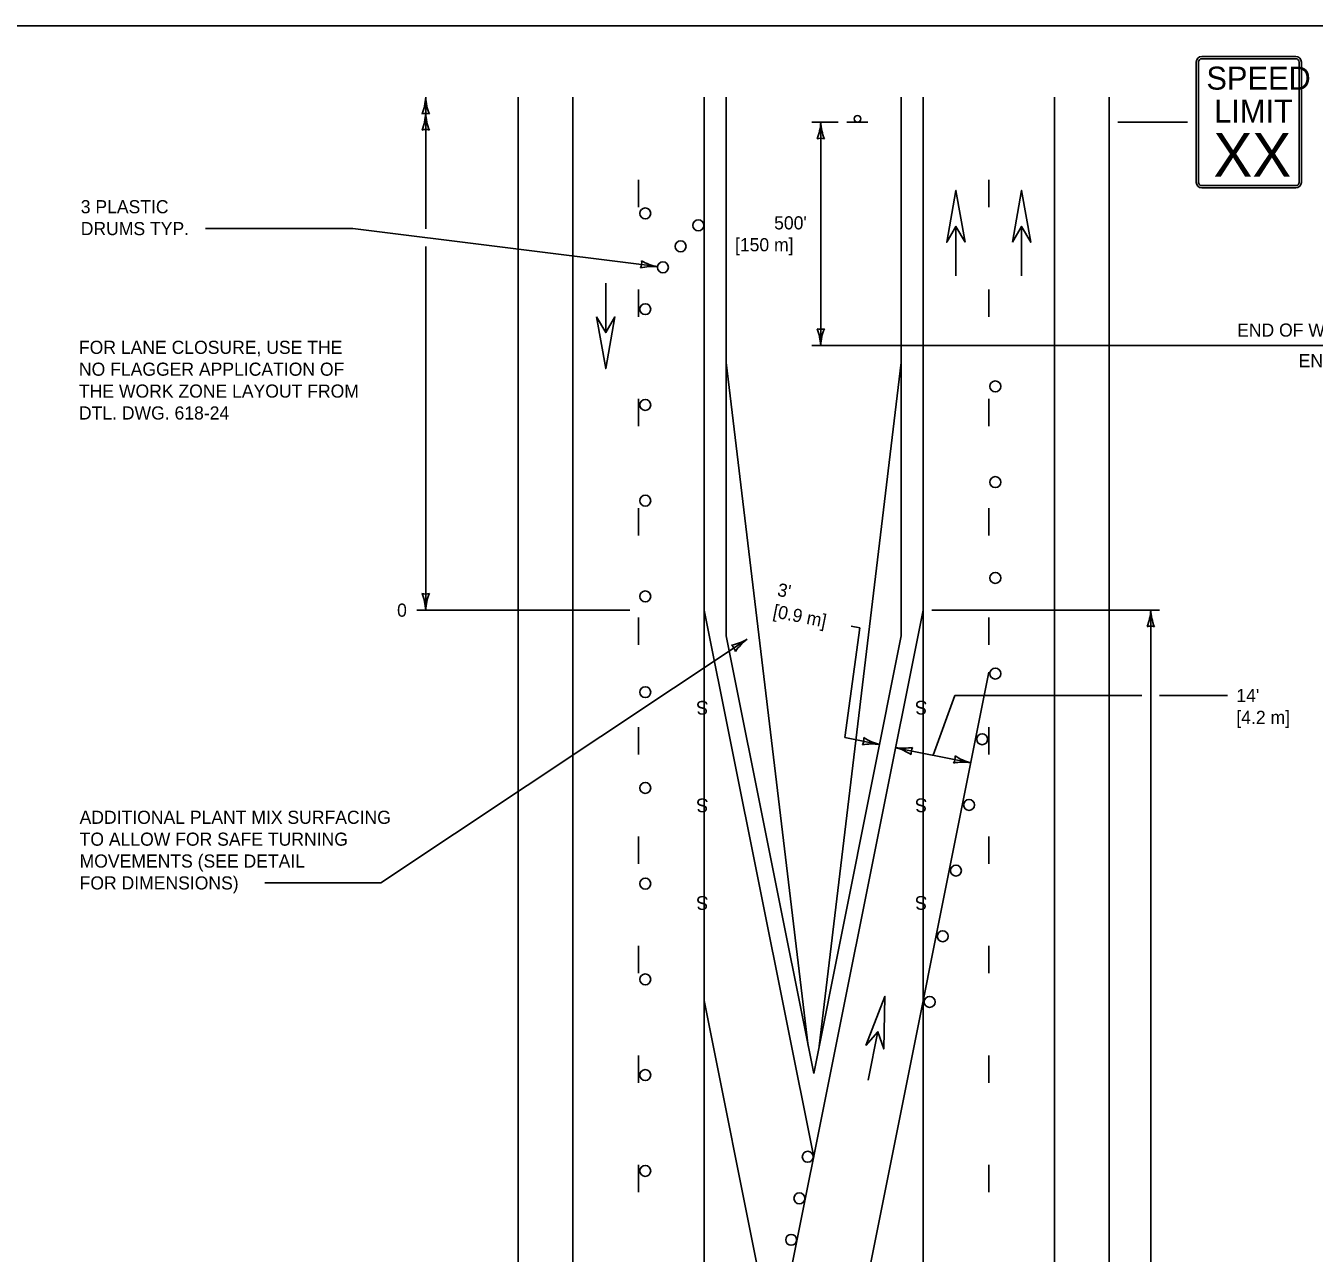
# Model space of a CAD drawing. Extents: x 49991.4 to 50021, y 49987.6 to 50011.4.
# Drawn here: x 50005.06 to 50010.95, y 49993.39 to 49999 of the extents above; entities that cross this region are included whole.
import ezdxf

# ---------------------------------------------------------------- set-up
doc = ezdxf.new("R2010")
doc.units = 0
for name, color, linetype in [('Level 1', 7, 'Continuous'), ('Level 2', 7, 'Continuous'), ('Level 3', 7, 'Continuous')]:
    doc.layers.add(name, color=color, linetype=linetype)

msp = doc.modelspace()

# ---------------------------------------------------------------- linework, layer by layer
at = {"layer": 'Level 1'}
for p, q in [((50010.4382, 49998.8586), (50010.8682, 49998.8586)), ((50010.4382, 49998.8486), (50010.8682, 49998.8486)), ((50010.4132, 49998.2836), (50010.4132, 49998.8336)), ((50010.4232, 49998.2836), (50010.4232, 49998.8336)), ((50010.8832, 49998.8336), (50010.8832, 49998.2836)), ((50010.8932, 49998.8336), (50010.8932, 49998.2836)), ((50007.315, 49988.2392), (50007.315, 49998.6725)), ((50007.565, 49988.2392), (50007.565, 49998.6725)), ((50008.165, 49996.3289), (50008.165, 49998.6725)), ((50008.265, 49996.2111), (50008.265, 49998.6725)), ((50009.065, 49996.2117), (50009.065, 49998.6725)), ((50009.165, 49996.3295), (50009.165, 49998.6725)), ((50009.765, 49988.1793), (50009.765, 49998.6725)), ((50010.015, 49988.1793), (50010.015, 49998.6725)), ((50008.913, 49998.5587), (50008.817, 49998.5587)), ((50007.865, 49998.1697), (50007.865, 49998.2947)), ((50009.465, 49998.1697), (50009.465, 49998.2947)), ((50010.8682, 49998.2686), (50010.4382, 49998.2686)), ((50010.8682, 49998.2586), (50010.4382, 49998.2586)), ((50009.3148, 49997.8565), (50009.3148, 49998.0823)), ((50009.315, 49997.8565), (50009.315, 49998.0823)), ((50009.6149, 49997.8565), (50009.6149, 49998.0823)), ((50009.6151, 49997.8565), (50009.6151, 49998.0823)), ((50007.7149, 49997.8226), (50007.7149, 49997.5968)), ((50007.7151, 49997.8226), (50007.7151, 49997.5968)), ((50007.865, 49997.6697), (50007.865, 49997.7947)), ((50009.465, 49997.6697), (50009.465, 49997.7947)), ((50008.265, 49997.4611), (50008.6399, 49994.3368)), ((50009.065, 49997.4611), (50008.6901, 49994.3368)), ((50007.865, 49997.1697), (50007.865, 49997.2947)), ((50009.465, 49997.1697), (50009.465, 49997.2947)), ((50007.865, 49996.6697), (50007.865, 49996.7947)), ((50009.465, 49996.6697), (50009.465, 49996.7947)), ((50007.865, 49989.8293), (50009.165, 49996.3295)), ((50008.165, 49994.5446), (50008.165, 49996.3289)), ((50008.665, 49993.8292), (50008.165, 49996.3289)), ((50009.165, 49994.5449), (50009.165, 49996.3295)), ((50007.865, 49996.1697), (50007.865, 49996.2947)), ((50009.465, 49996.1697), (50009.465, 49996.2947)), ((50008.665, 49994.2114), (50008.265, 49996.2111)), ((50008.665, 49994.2114), (50009.065, 49996.2117)), ((50008.165, 49989.5449), (50009.465, 49996.0449)), ((50007.865, 49995.6697), (50007.865, 49995.7947)), ((50009.465, 49995.6697), (50009.465, 49995.7947)), ((50007.865, 49995.1697), (50007.865, 49995.2947)), ((50009.465, 49995.1697), (50009.465, 49995.2947)), ((50007.865, 49994.6697), (50007.865, 49994.7947)), ((50009.465, 49994.6697), (50009.465, 49994.7947)), ((50008.165, 49991.3293), (50008.165, 49994.5446)), ((50008.4865, 49992.937), (50008.165, 49994.5446)), ((50009.165, 49991.3292), (50009.165, 49994.5449)), ((50008.9138, 49994.1814), (50008.9585, 49994.4029)), ((50008.914, 49994.1814), (50008.9587, 49994.4029)), ((50007.865, 49994.1697), (50007.865, 49994.2947)), ((50009.465, 49994.1697), (50009.465, 49994.2947)), ((50007.865, 49993.6697), (50007.865, 49993.7947)), ((50009.465, 49993.6697), (50009.465, 49993.7947))]:
    msp.add_line(p, q, dxfattribs=at)
for points in [[(49999.3835, 49998.9992), (50016.7501, 49998.9992), (50016.7501, 49987.7988), (49999.3835, 49987.7988)], [(50009.3568, 49998.0101), (50009.315, 49998.2465), (50009.2732, 49998.0101), (50009.315, 49998.0821)], [(50009.5731, 49998.0101), (50009.6149, 49998.2465), (50009.6567, 49998.0101), (50009.6149, 49998.0821)], [(50007.6731, 49997.669), (50007.7149, 49997.4326), (50007.7567, 49997.669), (50007.7149, 49997.597)], [(50008.903, 49994.3404), (50008.9908, 49994.5639), (50008.985, 49994.3238), (50008.9584, 49994.4028)]]:
    msp.add_lwpolyline(points, close=True, dxfattribs=at)
for centre, radius in [((50008.8651, 49998.5739), 0.0152), ((50007.8952, 49998.1417), 0.025), ((50008.1378, 49998.0873), 0.025), ((50008.0569, 49997.9913), 0.025), ((50007.9761, 49997.8954), 0.025), ((50007.8952, 49997.7042), 0.025), ((50009.4949, 49997.3514), 0.025), ((50007.8952, 49997.2667), 0.025), ((50009.4949, 49996.9139), 0.025), ((50007.8952, 49996.8292), 0.025), ((50009.4949, 49996.4764), 0.025), ((50007.8952, 49996.3917), 0.025), ((50009.4949, 49996.0389), 0.025), ((50007.8952, 49995.9542), 0.025), ((50009.4349, 49995.7389), 0.025), ((50007.8952, 49995.5167), 0.025), ((50009.3749, 49995.4389), 0.025), ((50009.3149, 49995.1389), 0.025), ((50007.8953, 49995.0793), 0.025), ((50009.2549, 49994.8389), 0.025), ((50007.8953, 49994.6418), 0.025), ((50009.1949, 49994.5389), 0.025), ((50007.8953, 49994.2043), 0.025), ((50008.6377, 49993.8311), 0.025), ((50007.8953, 49993.7668), 0.025), ((50008.5998, 49993.6413), 0.025), ((50008.562, 49993.4517), 0.025)]:
    msp.add_circle(centre, radius, dxfattribs=at)
for centre, radius, start, end in [((50010.4382, 49998.8336), 0.025, 90, 180), ((50010.4382, 49998.8336), 0.015, 90, 180), ((50010.8682, 49998.8336), 0.025, 0, 90), ((50010.8682, 49998.8336), 0.015, 0, 90), ((50010.4382, 49998.2836), 0.025, 180, 270), ((50010.4382, 49998.2836), 0.015, 180, 270), ((50010.8682, 49998.2836), 0.025, 270, 0), ((50010.8682, 49998.2836), 0.015, 270, 0)]:
    msp.add_arc(centre, radius, start, end, dxfattribs=at)
at = {"layer": 'Level 3'}
for p, q in [((50006.892, 49998.6723), (50006.892, 49998.0708)), ((50008.697, 49998.5586), (50008.657, 49998.5586)), ((50008.697, 49998.5586), (50008.697, 49997.5387)), ((50008.777, 49998.5586), (50008.697, 49998.5586)), ((50010.055, 49998.5586), (50010.3732, 49998.5586)), ((50005.8866, 49998.0724), (50006.5588, 49998.0724)), ((50006.5588, 49998.0724), (50007.9513, 49997.8985)), ((50006.892, 49997.9908), (50006.892, 49996.3289)), ((50008.697, 49997.5387), (50008.657, 49997.5387)), ((50011.6515, 49997.5387), (50008.697, 49997.5387)), ((50006.852, 49996.3289), (50007.825, 49996.3289)), ((50010.245, 49996.3295), (50009.205, 49996.3295)), ((50010.205, 49996.3295), (50010.205, 49989.5447)), ((50006.6874, 49995.0825), (50008.3613, 49996.1965)), ((50009.2108, 49995.6662), (50009.31, 49995.939)), ((50010.165, 49995.939), (50009.31, 49995.939)), ((50010.5563, 49995.939), (50010.245, 49995.939)), ((50008.9657, 49995.715), (50008.8079, 49995.7464)), ((50009.0392, 49995.7003), (50009.3824, 49995.632)), ((50006.6874, 49995.0825), (50006.1566, 49995.0825))]:
    msp.add_line(p, q, dxfattribs=at)
msp.add_lwpolyline([(50008.8361, 49996.2558), (50008.8753, 49996.248), (50008.8079, 49995.7464)], dxfattribs=at)
for centre, radius, start, end in [((50006.6699, 49998.6815), 0.2223, 337.45601, 357.63952), ((50007.1247, 49998.6838), 0.233, 182.82731, 202.07716), ((50006.892, 49998.5441), 0.0548, 72.13882, 107.86118), ((50006.6699, 49998.6081), 0.2223, 337.45601, 357.63952), ((50007.1247, 49998.6104), 0.233, 182.82731, 202.07716), ((50008.4749, 49998.5678), 0.2223, 337.45601, 357.63952), ((50008.9297, 49998.5701), 0.233, 182.82731, 202.07716), ((50006.892, 49998.4707), 0.0548, 72.13882, 107.86118), ((50008.697, 49998.4304), 0.0548, 72.13882, 107.86118), ((50007.8243, 49997.9163), 0.0548, 334.13882, 9.86118), ((50007.9302, 49997.6664), 0.233, 84.82731, 104.07716), ((50007.9912, 49998.1172), 0.2223, 239.45601, 259.63952), ((50008.697, 49997.667), 0.0548, 252.13882, 287.86118), ((50008.4643, 49997.5272), 0.233, 2.82731, 22.07716), ((50008.9191, 49997.5296), 0.2223, 157.45601, 177.63952), ((50006.892, 49996.4571), 0.0548, 252.13882, 287.86118), ((50006.6593, 49996.3174), 0.233, 2.82731, 22.07716), ((50007.1141, 49996.3197), 0.2223, 157.45601, 177.63952), ((50009.9829, 49996.3387), 0.2223, 337.45601, 357.63952), ((50010.4377, 49996.341), 0.233, 182.82731, 202.07716), ((50010.205, 49996.2013), 0.0548, 72.13882, 107.86118), ((50008.2459, 49996.3865), 0.2223, 281.10024, 301.28375), ((50008.4998, 49996.0091), 0.233, 126.47154, 145.72139), ((50008.2546, 49996.1255), 0.0548, 15.78305, 51.50541), ((50008.8401, 49995.7408), 0.0548, 330.52039, 6.24275), ((50008.9301, 49995.4847), 0.233, 81.20888, 100.45873), ((50009.0194, 49995.9307), 0.2223, 235.83758, 256.02109), ((50009.0733, 49995.9308), 0.233, 261.56669, 280.81654), ((50008.9868, 49995.4843), 0.2223, 56.19539, 76.3789), ((50009.1649, 49995.6753), 0.0548, 150.8782, 186.60056), ((50009.2567, 49995.657), 0.0548, 330.8782, 6.60056), ((50009.4391, 49995.858), 0.233, 236.66222, 255.91207), ((50009.348, 49995.4124), 0.2223, 81.09986, 101.28337)]:
    msp.add_arc(centre, radius, start, end, dxfattribs=at)

# ---------------------------------------------------------------- texts
at = {"layer": 'Level 1'}
for s, height, p in [('SPEED', 0.10512, (50010.4595, 49998.7072)), ('LIMIT', 0.10512, (50010.495, 49998.557)), ('XX', 0.19892, (50010.4918, 49998.3098))]:
    msp.add_text(s, height=height, dxfattribs=at).set_placement(p)
for p in [(50008.1842, 49995.9142), (50009.1842, 49995.9148), (50008.1842, 49995.4682), (50009.1842, 49995.4686), (50008.1842, 49995.0221), (50009.1842, 49995.0224)]:
    msp.add_text('S', height=0.0625, rotation=180, dxfattribs=at).set_placement(p)
at = {"layer": 'Level 2'}
for s, p in [('3 PLASTIC', (50005.3159, 49998.1424)), ('DRUMS TYP.', (50005.3159, 49998.0424)), ("500'", (50008.4842, 49998.0687)), ('[150 m]', (50008.3054, 49997.9687)), ('END OF WORK AREA OR', (50010.5997, 49997.5787)), ('FOR LANE CLOSURE, USE THE', (50005.3076, 49997.5)), ('END OF PROJECT', (50010.881, 49997.4387)), ('NO FLAGGER APPLICATION OF', (50005.3076, 49997.4)), ('THE WORK ZONE LAYOUT FROM', (50005.3076, 49997.3)), ('DTL. DWG. 618-24', (50005.3076, 49997.2)), ('0', (50006.7614, 49996.2989)), ("14'", (50010.5963, 49995.909)), ('[4.2 m]', (50010.5963, 49995.809)), ('ADDITIONAL PLANT MIX SURFACING ', (50005.3107, 49995.3525)), ('TO ALLOW FOR SAFE TURNING', (50005.3107, 49995.2525)), ('MOVEMENTS (SEE DETAIL', (50005.3107, 49995.1525)), ('FOR DIMENSIONS)', (50005.3107, 49995.0525))]:
    msp.add_text(s, height=0.06, dxfattribs=at).set_placement(p)
for s, p in [("3'", (50008.4953, 49996.395)), ('[0.9 m]', (50008.4758, 49996.297))]:
    msp.add_text(s, height=0.06, rotation=348.73938, dxfattribs=at).set_placement(p)

doc.saveas('drawing.dxf')
